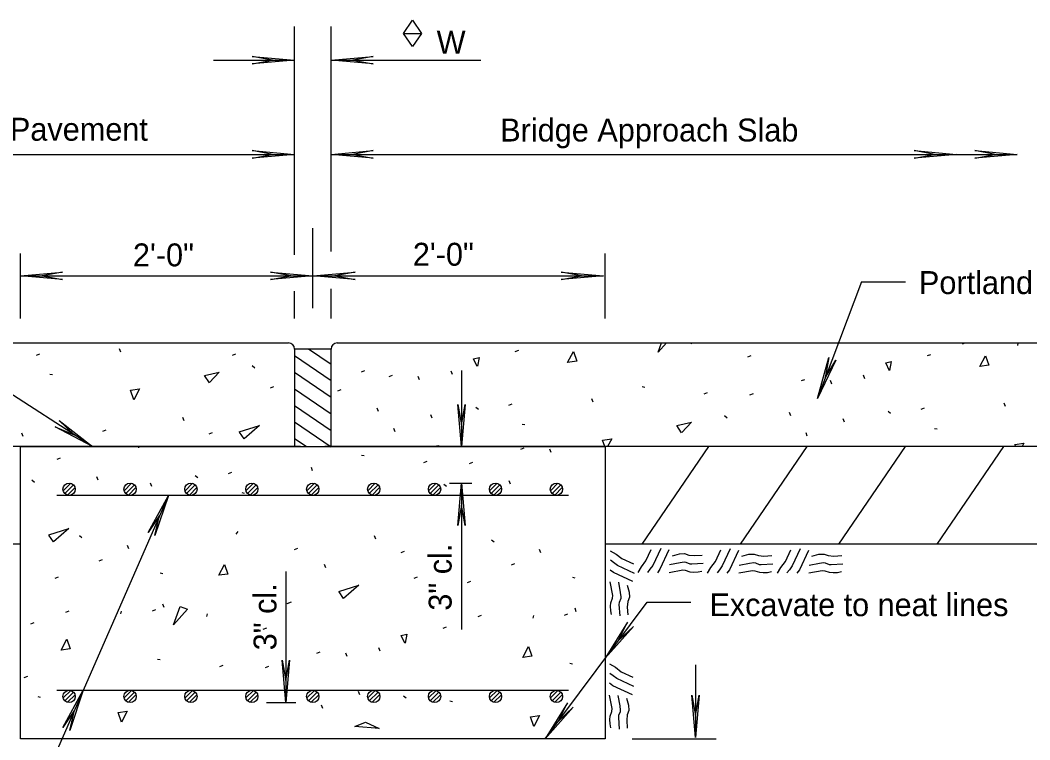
# Model space of a CAD drawing. Extents: x 1000 to 1036, y 1000 to 1022.7.
# Drawn here: x 1012.07 to 1018.98, y 1003.06 to 1007.99 of the extents above; entities that cross this region are included whole.
import ezdxf

# ---------------------------------------------------------------- set-up
doc = ezdxf.new("R2010")
doc.units = 0
for name, color, linetype in [('rd_Area Patterns Normal_z_n', 7, 'Continuous'), ('rd_Detail Annotation_z_n', 7, 'Continuous'), ('rd_Details_z_n', 7, 'Continuous'), ('rd_Dimensions_z_n', 7, 'Continuous'), ('rd_Misc Label_z_n', 7, 'Continuous'), ('rd_Symbols_z_n', 7, 'Continuous')]:
    doc.layers.add(name, color=color, linetype=linetype)

msp = doc.modelspace()

# ---------------------------------------------------------------- linework, layer by layer
at = {"layer": 'rd_Area Patterns Normal_z_n'}
for points in [[(1016.1096, 1004.3579), (1016.149, 1004.3348), (1016.1896, 1004.3038), (1016.2683, 1004.2672)], [(1016.2996, 1004.2077), (1016.3226, 1004.2471), (1016.3536, 1004.2877), (1016.3903, 1004.3664)], [(1016.4552, 1004.374), (1016.4004, 1004.2571), (1016.3812, 1004.2309), (1016.3647, 1004.2097)], [(1016.5113, 1004.3629), (1016.4492, 1004.2306), (1016.4323, 1004.2073)], [(1016.5345, 1004.3234), (1016.5828, 1004.3374), (1016.6179, 1004.3383), (1016.6476, 1004.3278), (1016.6855, 1004.3243), (1016.7393, 1004.3273)], [(1016.7751, 1004.2043), (1016.7981, 1004.2437), (1016.8291, 1004.2843), (1016.8658, 1004.363)], [(1016.9306, 1004.3706), (1016.8758, 1004.2537), (1016.8567, 1004.2275), (1016.8401, 1004.2063)], [(1016.9867, 1004.3595), (1016.9247, 1004.2272), (1016.9077, 1004.2039)], [(1017.01, 1004.32), (1017.0583, 1004.334), (1017.0934, 1004.3349), (1017.123, 1004.3244), (1017.1609, 1004.3209), (1017.2148, 1004.3239)], [(1017.2532, 1004.2043), (1017.2762, 1004.2437), (1017.3072, 1004.2843), (1017.3439, 1004.363)], [(1017.4087, 1004.3706), (1017.3539, 1004.2537), (1017.3348, 1004.2275), (1017.3182, 1004.2063)], [(1017.4648, 1004.3595), (1017.4028, 1004.2272), (1017.3858, 1004.2039)], [(1017.4881, 1004.32), (1017.5364, 1004.334), (1017.5715, 1004.3349), (1017.6011, 1004.3244), (1017.639, 1004.3209), (1017.6929, 1004.3239)], [(1016.2759, 1004.2023), (1016.159, 1004.2571), (1016.1328, 1004.2763), (1016.1116, 1004.2928)], [(1016.5155, 1004.2634), (1016.5866, 1004.2764), (1016.6152, 1004.2807), (1016.6266, 1004.2793), (1016.6531, 1004.2679), (1016.6674, 1004.2671), (1016.7461, 1004.2721)], [(1016.991, 1004.26), (1017.062, 1004.273), (1017.0906, 1004.2773), (1017.1021, 1004.2759), (1017.1285, 1004.2644), (1017.1428, 1004.2637), (1017.2216, 1004.2687)], [(1017.4691, 1004.26), (1017.5401, 1004.273), (1017.5687, 1004.2773), (1017.5802, 1004.2759), (1017.6066, 1004.2644), (1017.6209, 1004.2637), (1017.6997, 1004.2687)], [(1016.2648, 1004.1462), (1016.1325, 1004.2082), (1016.1092, 1004.2252)], [(1016.7367, 1004.2158), (1016.7103, 1004.2106), (1016.6795, 1004.2092), (1016.6567, 1004.2113), (1016.6252, 1004.222), (1016.6059, 1004.2242), (1016.5133, 1004.2066)], [(1017.2122, 1004.2123), (1017.1857, 1004.2072), (1017.155, 1004.2057), (1017.1321, 1004.2079), (1017.1007, 1004.2186), (1017.0814, 1004.2208), (1016.9887, 1004.2031)], [(1017.6903, 1004.2123), (1017.6638, 1004.2072), (1017.6331, 1004.2057), (1017.6102, 1004.2079), (1017.5788, 1004.2186), (1017.5595, 1004.2208), (1017.4668, 1004.2031)], [(1016.1177, 1003.9207), (1016.1125, 1003.9472), (1016.1111, 1003.9779), (1016.1132, 1004.0008), (1016.1239, 1004.0323), (1016.1261, 1004.0516), (1016.1085, 1004.1442)], [(1016.1653, 1004.1419), (1016.1783, 1004.0709), (1016.1826, 1004.0423), (1016.1812, 1004.0309), (1016.1698, 1004.0044), (1016.169, 1003.9901), (1016.174, 1003.9114)], [(1016.2253, 1004.123), (1016.2393, 1004.0746), (1016.2402, 1004.0396), (1016.2297, 1004.0099), (1016.2262, 1003.972), (1016.2292, 1003.9181)], [(1016.1054, 1003.5836), (1016.1448, 1003.5606), (1016.1853, 1003.5296), (1016.2641, 1003.4929)], [(1016.2717, 1003.428), (1016.1548, 1003.4828), (1016.1286, 1003.502), (1016.1074, 1003.5185)], [(1016.2606, 1003.3719), (1016.1283, 1003.434), (1016.1049, 1003.4509)], [(1016.1134, 1003.1465), (1016.1083, 1003.1729), (1016.1068, 1003.2037), (1016.109, 1003.2265), (1016.1197, 1003.258), (1016.1219, 1003.2773), (1016.1042, 1003.3699)], [(1016.161, 1003.3677), (1016.1741, 1003.2966), (1016.1784, 1003.268), (1016.177, 1003.2566), (1016.1655, 1003.2301), (1016.1648, 1003.2158), (1016.1697, 1003.1371)], [(1016.2211, 1003.3487), (1016.2351, 1003.3004), (1016.236, 1003.2653), (1016.2254, 1003.2356), (1016.222, 1003.1977), (1016.2249, 1003.1439)]]:
    msp.add_lwpolyline(points, dxfattribs=at)
at = {"layer": 'rd_Detail Annotation_z_n'}
for p, q in [((1012.5686, 1005.0697), (1010.611, 1006.3331)), ((1017.8287, 1006.1984), (1017.5265, 1005.4)), ((1017.8287, 1006.1984), (1018.1285, 1006.1984)), ((1013.0876, 1004.7365), (1012.1563, 1002.6063)), ((1015.6639, 1003.07), (1016.3611, 1004.0062)), ((1016.3611, 1004.0062), (1016.6609, 1004.0062))]:
    msp.add_line(p, q, dxfattribs=at)
at = {"layer": 'rd_Details_z_n'}
for p, q in [((1008.7913, 1005.7794), (1013.9081, 1005.7794)), ((1012.7623, 1005.715), (1012.7534, 1005.738)), ((1013.9498, 1005.7377), (1013.9498, 1005.0698)), ((1014.1998, 1005.7377), (1013.9498, 1005.7377)), ((1014.1998, 1005.6327), (1014.0462, 1005.7377)), ((1014.1998, 1005.0698), (1014.1998, 1005.7377)), ((1014.2415, 1005.7794), (1019.3582, 1005.7794)), ((1015.4602, 1005.7211), (1015.4833, 1005.7299)), ((1016.6651, 1005.7723), (1016.6666, 1005.7794)), ((1018.5198, 1005.7724), (1018.538, 1005.7794)), ((1018.8963, 1005.7611), (1018.8998, 1005.7788)), ((1012.1855, 1005.6964), (1012.2086, 1005.7053)), ((1013.546, 1005.7014), (1013.5236, 1005.6926)), ((1014.1998, 1005.5191), (1013.9498, 1005.6901)), ((1017.0714, 1005.692), (1017.0484, 1005.683)), ((1018.2798, 1005.6923), (1018.3029, 1005.7012)), ((1013.6604, 1005.6239), (1013.6782, 1005.6098)), ((1014.1998, 1005.4056), (1013.9498, 1005.5765)), ((1014.4278, 1005.5888), (1014.4049, 1005.5798)), ((1015.0191, 1005.5888), (1015.0279, 1005.5657)), ((1012.2769, 1005.5659), (1012.2948, 1005.5622)), ((1014.6181, 1005.5565), (1014.5951, 1005.5478)), ((1014.7936, 1005.5523), (1014.8025, 1005.5293)), ((1017.4377, 1005.5278), (1017.4147, 1005.519)), ((1017.6132, 1005.5236), (1017.6221, 1005.5005)), ((1017.8387, 1005.56), (1017.8476, 1005.5369)), ((1013.8056, 1005.4784), (1013.7827, 1005.4694)), ((1014.1998, 1005.292), (1013.9498, 1005.4629)), ((1014.2664, 1005.459), (1014.2434, 1005.45)), ((1016.3276, 1005.481), (1016.3453, 1005.4773)), ((1015.9927, 1005.3729), (1015.9838, 1005.3958)), ((1016.7732, 1005.4375), (1016.7503, 1005.4285)), ((1017.086, 1005.4302), (1017.063, 1005.4213)), ((1014.1998, 1005.1784), (1013.9498, 1005.3494)), ((1014.5141, 1005.3347), (1014.523, 1005.3116)), ((1015.1898, 1005.3409), (1015.2077, 1005.3269)), ((1015.4159, 1005.3543), (1015.439, 1005.3632)), ((1017.3337, 1005.306), (1017.3426, 1005.2829)), ((1018.0094, 1005.3122), (1018.0273, 1005.2981)), ((1018.2355, 1005.3256), (1018.2586, 1005.3344)), ((1018.8123, 1005.3441), (1018.8034, 1005.3671)), ((1013.1946, 1005.2471), (1013.1857, 1005.2702)), ((1014.1998, 1005.0666), (1013.9498, 1005.2376)), ((1014.8809, 1005.2904), (1014.8898, 1005.2674)), ((1016.8908, 1005.2817), (1016.9086, 1005.2676)), ((1017.7005, 1005.2617), (1017.7094, 1005.2386)), ((1012.0828, 1005.1647), (1012.0917, 1005.1417)), ((1012.6596, 1005.1832), (1012.6365, 1005.1744)), ((1013.3668, 1005.1572), (1013.3898, 1005.1661)), ((1014.6265, 1005.1959), (1014.6352, 1005.173)), ((1015.5073, 1005.2237), (1015.5252, 1005.2201)), ((1017.4461, 1005.1672), (1017.4548, 1005.1442)), ((1018.327, 1005.195), (1018.3448, 1005.1914)), ((1014.0291, 1005.0698), (1013.9498, 1005.124)), ((1013.9914, 1005.0698), (1008.7913, 1005.0698)), ((1012.0749, 1005.0698), (1016.0746, 1005.0698)), ((1012.0749, 1003.07), (1012.0749, 1005.0698)), ((1012.8453, 1005.0698), (1012.8439, 1005.0735)), ((1012.8803, 1005.0698), (1012.8838, 1005.0606)), ((1019.3582, 1005.0698), (1014.1581, 1005.0698)), ((1015.519, 1005.0591), (1015.4961, 1005.0504)), ((1015.6945, 1005.0549), (1015.7034, 1005.0319)), ((1015.9283, 1005.0698), (1015.9289, 1005.0683)), ((1016.0746, 1005.0698), (1016.0746, 1003.07)), ((1016.3274, 1004.4032), (1016.7832, 1005.0698)), ((1017.0003, 1004.4032), (1017.4562, 1005.0698)), ((1017.6733, 1004.4032), (1018.1291, 1005.0698)), ((1018.3463, 1004.4032), (1018.8021, 1005.0698)), ((1012.3477, 1004.9903), (1012.3248, 1004.9813)), ((1014.4089, 1005.0123), (1014.4266, 1005.0086)), ((1014.8545, 1004.9688), (1014.8316, 1004.9598)), ((1015.1673, 1004.9616), (1015.1444, 1004.9526)), ((1013.4973, 1004.8856), (1013.5203, 1004.8945)), ((1014.0741, 1004.9042), (1014.0651, 1004.9272)), ((1012.1525, 1004.8418), (1012.1704, 1004.8277)), ((1012.3678, 1004.7675), (1012.4191, 1004.8188)), ((1012.5954, 1004.8661), (1012.6043, 1004.843)), ((1012.7844, 1004.7675), (1012.8357, 1004.8188)), ((1012.9622, 1004.8218), (1012.9711, 1004.7987)), ((1013.201, 1004.7675), (1013.2524, 1004.8188)), ((1013.2712, 1004.8723), (1013.289, 1004.8582)), ((1013.6176, 1004.7675), (1013.669, 1004.8188)), ((1014.0343, 1004.7675), (1014.0856, 1004.8188)), ((1014.451, 1004.7675), (1014.5022, 1004.8188)), ((1014.8675, 1004.7675), (1014.9189, 1004.8188)), ((1015.2841, 1004.7675), (1015.3356, 1004.8188)), ((1015.4151, 1004.8373), (1015.4239, 1004.8142)), ((1015.7008, 1004.7675), (1015.7521, 1004.8188)), ((1012.3784, 1004.7487), (1012.4381, 1004.8082)), ((1012.3975, 1004.7378), (1012.4487, 1004.7894)), ((1012.7951, 1004.7487), (1012.8547, 1004.8082)), ((1012.8141, 1004.7378), (1012.8654, 1004.7894)), ((1013.2117, 1004.7487), (1013.2713, 1004.8082)), ((1013.2306, 1004.7378), (1013.2821, 1004.7894)), ((1013.5887, 1004.7551), (1013.6065, 1004.7514)), ((1013.6282, 1004.7487), (1013.688, 1004.8082)), ((1013.6473, 1004.7378), (1013.6987, 1004.7894)), ((1014.0449, 1004.7487), (1014.1046, 1004.8082)), ((1014.064, 1004.7378), (1014.1152, 1004.7894)), ((1014.4616, 1004.7487), (1014.5212, 1004.8082)), ((1014.4806, 1004.7378), (1014.5319, 1004.7894)), ((1014.8782, 1004.7487), (1014.9378, 1004.8082)), ((1014.8971, 1004.7378), (1014.9486, 1004.7894)), ((1014.9721, 1004.813), (1014.99, 1004.799)), ((1015.2948, 1004.7487), (1015.3545, 1004.8082)), ((1015.3138, 1004.7378), (1015.3652, 1004.7894)), ((1015.7115, 1004.7487), (1015.7711, 1004.8082)), ((1015.7305, 1004.7378), (1015.7817, 1004.7894)), ((1015.8246, 1004.7365), (1012.3249, 1004.7365)), ((1013.5503, 1004.4715), (1013.5644, 1004.4893)), ((1012.0749, 1004.4032), (1008.7913, 1004.4032)), ((1012.4964, 1004.445), (1012.4786, 1004.4591)), ((1014.5063, 1004.4363), (1014.4975, 1004.4594)), ((1015.316, 1004.4163), (1015.2982, 1004.4304)), ((1019.3582, 1004.4032), (1016.0746, 1004.4032)), ((1012.8158, 1004.3713), (1012.807, 1004.3944)), ((1013.9713, 1004.3724), (1013.9482, 1004.3636)), ((1014.6786, 1004.3464), (1014.7015, 1004.3553)), ((1015.6354, 1004.3426), (1015.6266, 1004.3656)), ((1012.614, 1004.2892), (1012.637, 1004.2982)), ((1015.4336, 1004.2605), (1015.4566, 1004.2695)), ((1013.031, 1004.2053), (1013.0487, 1004.2018)), ((1014.1644, 1004.2397), (1014.1556, 1004.2627)), ((1012.3133, 1004.1699), (1012.3364, 1004.1787)), ((1014.7692, 1004.1702), (1014.7921, 1004.1789)), ((1015.133, 1004.1412), (1015.156, 1004.15)), ((1015.8506, 1004.1766), (1015.8683, 1004.1731)), ((1013.0578, 1003.9695), (1013.0489, 1003.9926)), ((1013.927, 1004.0056), (1013.8965, 1003.9939)), ((1012.3861, 1003.9371), (1012.4091, 1003.9459)), ((1012.7626, 1003.9257), (1012.7661, 1003.9434)), ((1012.9984, 1003.9525), (1012.9753, 1003.9437)), ((1013.351, 1003.9082), (1013.3547, 1003.9259)), ((1015.818, 1003.9238), (1015.7949, 1003.9149)), ((1015.8774, 1003.9407), (1015.8685, 1003.9638)), ((1012.1461, 1003.857), (1012.1692, 1003.8658)), ((1015.2057, 1003.9083), (1015.2287, 1003.9172)), ((1015.5822, 1003.897), (1015.5857, 1003.9147)), ((1013.7573, 1003.8279), (1013.7343, 1003.8189)), ((1014.9657, 1003.8282), (1014.9888, 1003.8371)), ((1014.1236, 1003.6637), (1014.1006, 1003.655)), ((1014.2991, 1003.6595), (1014.308, 1003.6364)), ((1014.5246, 1003.6959), (1014.5335, 1003.6729)), ((1013.0135, 1003.6169), (1013.0312, 1003.6132)), ((1013.4591, 1003.5734), (1013.4362, 1003.5644)), ((1015.8331, 1003.5882), (1015.8508, 1003.5844)), ((1013.7719, 1003.5662), (1013.7489, 1003.5572)), ((1012.1018, 1003.4902), (1012.1249, 1003.4991)), ((1012.3249, 1003.4033), (1015.8246, 1003.4033)), ((1012.3678, 1003.3502), (1012.4191, 1003.4016)), ((1012.3784, 1003.3316), (1012.4381, 1003.391)), ((1012.3975, 1003.3207), (1012.4487, 1003.3722)), ((1012.7844, 1003.3502), (1012.8357, 1003.4016)), ((1012.7951, 1003.3316), (1012.8547, 1003.391)), ((1012.8141, 1003.3207), (1012.8654, 1003.3722)), ((1013.201, 1003.3502), (1013.2524, 1003.4016)), ((1013.2117, 1003.3316), (1013.2713, 1003.391)), ((1013.2306, 1003.3207), (1013.2821, 1003.3722)), ((1013.6176, 1003.3502), (1013.669, 1003.4016)), ((1013.6282, 1003.3316), (1013.688, 1003.391)), ((1013.6473, 1003.3207), (1013.6987, 1003.3722)), ((1014.0343, 1003.3502), (1014.0856, 1003.4016)), ((1014.0449, 1003.3316), (1014.1046, 1003.391)), ((1014.064, 1003.3207), (1014.1152, 1003.3722)), ((1014.3864, 1003.3976), (1014.3953, 1003.3745)), ((1014.451, 1003.3502), (1014.5022, 1003.4016)), ((1014.4616, 1003.3316), (1014.5212, 1003.391)), ((1014.4806, 1003.3207), (1014.5319, 1003.3722)), ((1014.8675, 1003.3502), (1014.9189, 1003.4016)), ((1014.8782, 1003.3316), (1014.9378, 1003.391)), ((1014.8971, 1003.3207), (1014.9486, 1003.3722)), ((1015.2841, 1003.3502), (1015.3356, 1003.4016)), ((1015.2948, 1003.3316), (1015.3545, 1003.391)), ((1015.3138, 1003.3207), (1015.3652, 1003.3722)), ((1015.7008, 1003.3502), (1015.7521, 1003.4016)), ((1015.7115, 1003.3316), (1015.7711, 1003.391)), ((1015.7305, 1003.3207), (1015.7817, 1003.3722)), ((1012.1932, 1003.3596), (1012.2111, 1003.356)), ((1014.132, 1003.3031), (1014.1407, 1003.2801)), ((1014.6953, 1003.3648), (1014.7132, 1003.3507)), ((1015.0129, 1003.3309), (1015.0307, 1003.3273)), ((1016.0746, 1003.07), (1012.0749, 1003.07))]:
    msp.add_line(p, q, dxfattribs=at)
for points in [[(1015.8572, 1005.7205), (1015.8801, 1005.6549), (1015.8181, 1005.646), (1015.8572, 1005.7205)], [(1016.4936, 1005.7794), (1016.4361, 1005.7155), (1016.4601, 1005.7794)], [(1015.1991, 1005.6173), (1015.1737, 1005.6708), (1015.2123, 1005.6802), (1015.2009, 1005.6192)], [(1018.0187, 1005.5886), (1017.9934, 1005.6421), (1018.0319, 1005.6514), (1018.0205, 1005.5904)], [(1018.6768, 1005.6917), (1018.6997, 1005.6261), (1018.6378, 1005.6173), (1018.6768, 1005.6917)], [(1013.3674, 1005.5055), (1013.3337, 1005.556), (1013.4338, 1005.5786), (1013.3684, 1005.5077)], [(1012.85, 1005.3906), (1012.8271, 1005.4562), (1012.889, 1005.4651), (1012.85, 1005.3906)], [(1016.5979, 1005.1634), (1016.5641, 1005.2139), (1016.6642, 1005.2364), (1016.5988, 1005.1656)], [(1013.5718, 1005.1714), (1013.7101, 1005.2139), (1013.6045, 1005.124), (1013.5737, 1005.1695)], [(1016.073, 1005.0698), (1016.0575, 1005.1141), (1016.1195, 1005.1229), (1016.0916, 1005.0698)], [(1018.8825, 1005.0698), (1018.8771, 1005.0854), (1018.9391, 1005.0942), (1018.9263, 1005.0698)], [(1014.9083, 1005.0698), (1014.9303, 1005.0787)], [(1014.9303, 1005.0787), (1014.9489, 1005.0698)], [(1012.2688, 1004.4661), (1012.4071, 1004.5086), (1012.3015, 1004.4187), (1012.2707, 1004.4642)], [(1013.4717, 1004.2639), (1013.4946, 1004.1983), (1013.4327, 1004.1894), (1013.4717, 1004.2639)], [(1014.2524, 1004.0791), (1014.3907, 1004.1216), (1014.2851, 1004.0317), (1014.2543, 1004.0772)], [(1013.2184, 1003.9585), (1013.122, 1003.8514), (1013.1688, 1003.976), (1013.2184, 1003.9585)], [(1014.7046, 1003.7245), (1014.6792, 1003.778), (1014.7178, 1003.7873), (1014.7064, 1003.7263)], [(1012.3936, 1003.7522), (1012.4166, 1003.6866), (1012.3546, 1003.6778), (1012.3936, 1003.7522)], [(1015.5506, 1003.7025), (1015.5735, 1003.6369), (1015.5115, 1003.628), (1015.5506, 1003.7025)], [(1012.7663, 1003.1844), (1012.7434, 1003.25), (1012.8054, 1003.2589), (1012.7663, 1003.1844)], [(1015.5859, 1003.1557), (1015.563, 1003.2213), (1015.625, 1003.2301), (1015.5859, 1003.1557)], [(1014.4358, 1003.1858), (1014.5286, 1003.1414), (1014.3625, 1003.1562), (1014.4358, 1003.1858)]]:
    msp.add_lwpolyline(points, dxfattribs=at)
for centre in [(1012.4082, 1004.7785), (1012.8249, 1004.7785), (1013.2415, 1004.7785), (1013.6581, 1004.7785), (1014.0747, 1004.7785), (1014.4914, 1004.7785), (1014.908, 1004.7785), (1015.3246, 1004.7785), (1015.7413, 1004.7785), (1012.4082, 1003.3613), (1012.8249, 1003.3613), (1013.2415, 1003.3613), (1013.6581, 1003.3613), (1014.0747, 1003.3613), (1014.4914, 1003.3613), (1014.908, 1003.3613), (1015.3246, 1003.3613), (1015.7413, 1003.3613)]:
    msp.add_circle(centre, 0.042, dxfattribs=at)
for centre, start, end in [((1013.9081, 1005.7377), 0, 90), ((1014.2415, 1005.7377), 90, 180)]:
    msp.add_arc(centre, 0.0417, start, end, dxfattribs=at)
at = {"layer": 'rd_Dimensions_z_n'}
for p, q in [((1013.9498, 1006.3818), (1013.9498, 1007.9435)), ((1014.1998, 1006.4051), (1014.1998, 1007.9435)), ((1013.3958, 1007.7137), (1013.9498, 1007.7137)), ((1014.1998, 1007.7137), (1015.2243, 1007.7137)), ((1008.7665, 1007.0695), (1013.9498, 1007.0695)), ((1014.1998, 1007.0695), (1018.8932, 1007.0695)), ((1014.0748, 1006.0177), (1014.0748, 1006.5653)), ((1012.075, 1005.947), (1012.075, 1006.3919)), ((1016.0746, 1005.947), (1016.0746, 1006.3919)), ((1012.0749, 1006.2376), (1014.0747, 1006.2376)), ((1014.0747, 1006.2376), (1016.0627, 1006.2376)), ((1013.9498, 1005.947), (1013.9498, 1006.1333)), ((1014.1998, 1005.947), (1014.1998, 1006.1489)), ((1015.0923, 1005.5911), (1015.0923, 1005.0698)), ((1015.0089, 1004.8205), (1015.1621, 1004.8205)), ((1015.0923, 1004.8205), (1015.0923, 1003.8179)), ((1013.8913, 1004.216), (1013.8913, 1003.3193)), ((1016.6931, 1003.5766), (1016.6931, 1003.0796)), ((1013.7582, 1003.3193), (1013.9588, 1003.3193)), ((1016.2595, 1003.07), (1016.8338, 1003.07))]:
    msp.add_line(p, q, dxfattribs=at)
at = {"layer": 'rd_Misc Label_z_n'}
for points in [[(1013.6607, 1007.739), (1013.9498, 1007.7137), (1013.6607, 1007.6884), (1013.7998, 1007.7137), (1013.6607, 1007.739)], [(1014.4889, 1007.6884), (1014.1998, 1007.7137), (1014.4889, 1007.739), (1014.3498, 1007.7137), (1014.4889, 1007.6884)], [(1013.6607, 1007.0948), (1013.9498, 1007.0695), (1013.6607, 1007.0442), (1013.7998, 1007.0695), (1013.6607, 1007.0948)], [(1014.4889, 1007.0442), (1014.1998, 1007.0695), (1014.4889, 1007.0948), (1014.3498, 1007.0695), (1014.4889, 1007.0442)], [(1018.1882, 1007.0948), (1018.4773, 1007.0695), (1018.1882, 1007.0442), (1018.3273, 1007.0695), (1018.1882, 1007.0948)], [(1018.6041, 1007.0948), (1018.8932, 1007.0695), (1018.6041, 1007.0442), (1018.7432, 1007.0695), (1018.6041, 1007.0948)], [(1012.3641, 1006.2124), (1012.075, 1006.2377), (1012.3641, 1006.263), (1012.225, 1006.2377), (1012.3641, 1006.2124)], [(1013.7857, 1006.263), (1014.0748, 1006.2377), (1013.7857, 1006.2124), (1013.9248, 1006.2377), (1013.7857, 1006.263)], [(1014.3639, 1006.2124), (1014.0748, 1006.2377), (1014.3639, 1006.263), (1014.2248, 1006.2377), (1014.3639, 1006.2124)], [(1015.7736, 1006.263), (1016.0627, 1006.2377), (1015.7736, 1006.2124), (1015.9127, 1006.2377), (1015.7736, 1006.263)], [(1017.6525, 1005.6615), (1017.5265, 1005.4), (1017.6052, 1005.6794), (1017.5796, 1005.5403), (1017.6525, 1005.6615)], [(1015.1176, 1005.3589), (1015.0923, 1005.0697), (1015.067, 1005.3589), (1015.0923, 1005.2197), (1015.1176, 1005.3589)], [(1012.3394, 1005.2478), (1012.5686, 1005.0697), (1012.312, 1005.2053), (1012.4426, 1005.1511), (1012.3394, 1005.2478)], [(1015.067, 1004.5313), (1015.0923, 1004.8204), (1015.1176, 1004.5313), (1015.0923, 1004.6704), (1015.067, 1004.5313)], [(1012.9487, 1004.4817), (1013.0877, 1004.7365), (1012.995, 1004.4614), (1013.0276, 1004.599), (1012.9487, 1004.4817)], [(1016.227, 1003.8685), (1016.0746, 1003.6215), (1016.2675, 1003.8383), (1016.1641, 1003.7418), (1016.227, 1003.8685)], [(1013.9167, 1003.6084), (1013.8914, 1003.3192), (1013.8661, 1003.6084), (1013.8914, 1003.4692), (1013.9167, 1003.6084)], [(1012.3658, 1003.1484), (1012.5047, 1003.4032), (1012.4121, 1003.1282), (1012.4447, 1003.2658), (1012.3658, 1003.1484)], [(1016.7184, 1003.3687), (1016.6931, 1003.0796), (1016.6678, 1003.3687), (1016.6931, 1003.2296), (1016.7184, 1003.3687)], [(1015.8163, 1003.317), (1015.6639, 1003.07), (1015.8569, 1003.2868), (1015.7535, 1003.1903), (1015.8163, 1003.317)]]:
    msp.add_lwpolyline(points, dxfattribs=at)
at = {"layer": 'rd_Symbols_z_n'}
msp.add_lwpolyline([(1014.6958, 1007.8973), (1014.757, 1007.9873), (1014.8182, 1007.8973)], dxfattribs=at)
msp.add_lwpolyline([(1014.6958, 1007.8973), (1014.8182, 1007.8973), (1014.757, 1007.8073)], close=True, dxfattribs=at)

# ---------------------------------------------------------------- texts
at = {"layer": 'rd_Detail Annotation_z_n'}
for s, height, p in [('Portland Cement Concrete Pavement', 0.15675, (1018.2207, 1006.1137)), ('Excavate to neat lines', 0.15625, (1016.7885, 1003.91))]:
    msp.add_text(s, height=height, dxfattribs=at).set_placement(p)
at = {"layer": 'rd_Dimensions_z_n'}
for s, height, p in [('W', 0.1567, (1014.9223, 1007.7582)), ('Roadway Approach Pavement', 0.15675, (1010.1156, 1007.1627)), ('Bridge Approach Slab', 0.15675, (1015.357, 1007.1573)), ('2\'-0"', 0.15675, (1012.8448, 1006.3032)), ('2\'-0"', 0.15675, (1014.7592, 1006.3076))]:
    msp.add_text(s, height=height, dxfattribs=at).set_placement(p)
for p in [(1015.0244, 1003.9474), (1013.8266, 1003.6761)]:
    msp.add_text('3" cl.', height=0.15675, rotation=90, dxfattribs=at).set_placement(p)

doc.saveas('drawing.dxf')
